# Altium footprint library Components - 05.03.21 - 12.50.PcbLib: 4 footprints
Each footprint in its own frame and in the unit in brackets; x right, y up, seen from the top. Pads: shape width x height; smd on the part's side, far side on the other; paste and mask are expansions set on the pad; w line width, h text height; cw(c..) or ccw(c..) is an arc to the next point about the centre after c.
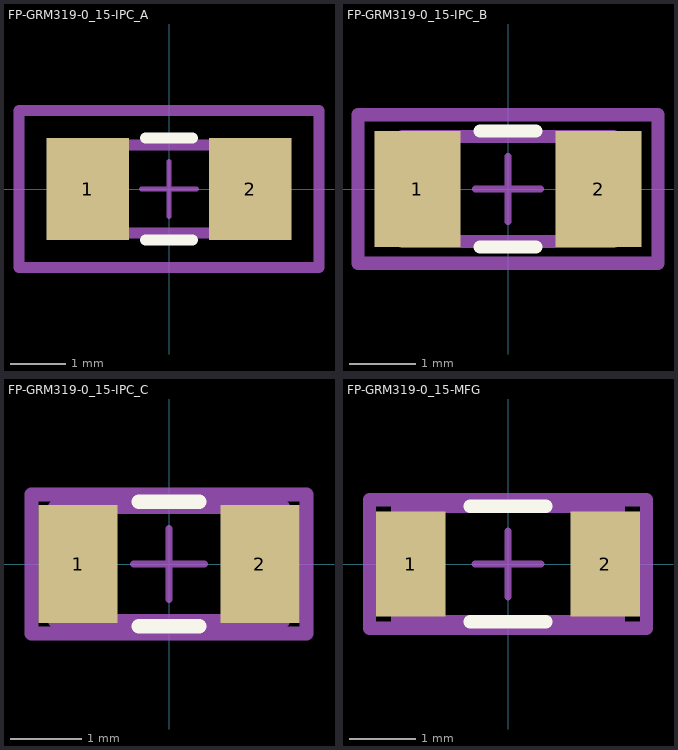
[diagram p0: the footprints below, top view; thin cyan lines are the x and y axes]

## FP-GRM319-0_15-IPC_A [mm]
pads (2):
  rect 1.506x1.858 smd paste+0 mask+0: 1(-1.476,0) 2(1.476,0)
Top Overlay:
  lines w0.2: -0.423,-0.929 0.423,-0.929 ; -0.423,0.929 0.423,0.929
Mechanical 5:
  lines w0.2: -2.729,-1.429 2.729,-1.429 2.729,1.429 -2.729,1.429 -2.729,-1.429
  text ".Designator" at 0,0.188 h1
Mechanical 13:
  lines w0.2: -1.6,-0.8 1.6,-0.8 1.6,0.8 -1.6,0.8 -1.6,-0.8
Mechanical 15:
  lines w0.2: -2.729,-1.429 2.729,-1.429 2.729,1.429 -2.729,1.429 -2.729,-1.429
Mechanical 16:
  lines w0.1: -0.5,0 0.5,0 ; 0,-0.5 0,0.5
3D body "Cap_Murata_GRM3195C1H273JA01D_eec.STEP": height 0.25, standoff 0, extent -2.729,-1.429 2.729,1.429

## FP-GRM319-0_15-IPC_B [mm]
pads (2):
  rect 1.306x1.758 smd paste+0 mask+0: 1(-1.376,0) 2(1.376,0)
Top Overlay:
  lines w0.2: -0.423,-0.879 0.423,-0.879 ; -0.423,0.879 0.423,0.879
Mechanical 5:
  lines w0.2: -2.279,-1.129 2.279,-1.129 2.279,1.129 -2.279,1.129 -2.279,-1.129
  text ".Designator" at 0,0.188 h1
Mechanical 13:
  lines w0.2: -1.6,-0.8 1.6,-0.8 1.6,0.8 -1.6,0.8 -1.6,-0.8
Mechanical 15:
  lines w0.2: -2.279,-1.129 2.279,-1.129 2.279,1.129 -2.279,1.129 -2.279,-1.129
Mechanical 16:
  lines w0.1: -0.5,0 0.5,0 ; 0,-0.5 0,0.5
3D body "Cap_Murata_GRM3195C1H273JA01D_eec.STEP": height 0.25, standoff 0, extent -2.279,-1.129 2.279,1.129

## FP-GRM319-0_15-IPC_C [mm]
pads (2):
  rect 1.106x1.658 smd paste+0 mask+0: 1(-1.276,0) 2(1.276,0)
Top Overlay:
  lines w0.2: -0.423,-0.875 0.423,-0.875 ; -0.423,0.875 0.423,0.875
Mechanical 5:
  lines w0.2: -1.929,-0.975 1.929,-0.975 1.929,0.975 -1.929,0.975 -1.929,-0.975
  text ".Designator" at 0,0.188 h1
Mechanical 13:
  lines w0.2: -1.6,-0.8 1.6,-0.8 1.6,0.8 -1.6,0.8 -1.6,-0.8
Mechanical 15:
  lines w0.2: -1.929,-0.975 1.929,-0.975 1.929,0.975 -1.929,0.975 -1.929,-0.975
Mechanical 16:
  lines w0.1: -0.5,0 0.5,0 ; 0,-0.5 0,0.5
3D body "Cap_Murata_GRM3195C1H273JA01D_eec.STEP": height 0.25, standoff 0, extent -1.929,-0.975 1.929,0.975

## FP-GRM319-0_15-MFG [mm]
pads (2):
  rect 1.05x1.6 smd paste+0 mask+0: 1(-1.475,0) 2(1.475,0)
Top Overlay:
  lines w0.2: -0.575,-0.875 0.575,-0.875 ; -0.575,0.875 0.575,0.875
Mechanical 5:
  lines w0.2: -2.1,-0.975 2.1,-0.975 2.1,0.975 -2.1,0.975 -2.1,-0.975
  text ".Designator" at 0,0.188 h1
Mechanical 13:
  lines w0.2: -1.675,-0.875 1.675,-0.875 1.675,0.875 -1.675,0.875 -1.675,-0.875
Mechanical 15:
  lines w0.2: -2.1,-0.975 2.1,-0.975 2.1,0.975 -2.1,0.975 -2.1,-0.975
Mechanical 16:
  lines w0.1: -0.5,0 0.5,0 ; 0,-0.5 0,0.5
3D body "Cap_Murata_GRM3195C1H273JA01D_eec.STEP": height 0.25, standoff 0, extent -2.1,-0.975 2.1,0.975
